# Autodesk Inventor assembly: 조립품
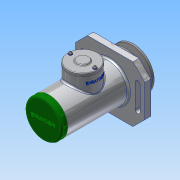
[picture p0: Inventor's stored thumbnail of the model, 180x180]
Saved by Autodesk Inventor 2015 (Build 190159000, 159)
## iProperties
Created: 2017-10
Part Number: 조립품
Document SubType Name: Assembly
Designer: Administrator
Author: Administrator
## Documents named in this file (20)
- C:\Users\Administrator\Desktop\471007V1009\조립품.iam
- C:\Users\Administrator\Desktop\471007V1009\본체.ipt
- C:\Users\Administrator\Desktop\471007V1009\V-벨트풀리.ipt
- C:\Users\Administrator\Desktop\471007V1009\너트 M10.ipt
- C:\Users\Administrator\Desktop\471007V1009\멈춤링 15 x 1.ipt
- C:\Users\Administrator\Desktop\471007V1009\멈춤링 35x1.6.ipt
- C:\Users\Administrator\Desktop\471007V1009\베어링 15 x 35 x 11.ipt
- C:\Users\Administrator\Desktop\471007V1009\볼트 M4 x 10.ipt
- C:\Users\Administrator\Desktop\471007V1009\부시1.ipt
- C:\Users\Administrator\Desktop\471007V1009\부시2.ipt
- C:\Users\Administrator\Desktop\471007V1009\사이드 커버.ipt
- 사이드 커버.ipt
- C:\Users\Administrator\Desktop\471007V1009\십자볼트 M3 x 10.ipt
- C:\Users\Administrator\Desktop\471007V1009\오일 실 15 25 7.ipt
- C:\Users\Administrator\Desktop\471007V1009\와셔 3x6.ipt
- C:\Users\Administrator\Desktop\471007V1009\와셔 4x16.ipt
- C:\Users\Administrator\Desktop\471007V1009\와셔 10x21.ipt
- C:\Users\Administrator\Desktop\471007V1009\축.ipt
- C:\Users\Administrator\Desktop\471007V1009\키 4 x 4 x 18.ipt
- C:\Users\Administrator\Desktop\471007V1009\탑 커버.ipt
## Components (2 placed, 2 different names)
1. V-벨트풀리:1 — 각도:2
2. ISO 4017 M4 x 10:1
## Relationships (1: Angle 1)
- 각도:2 [Angle]: V-벨트풀리:1
